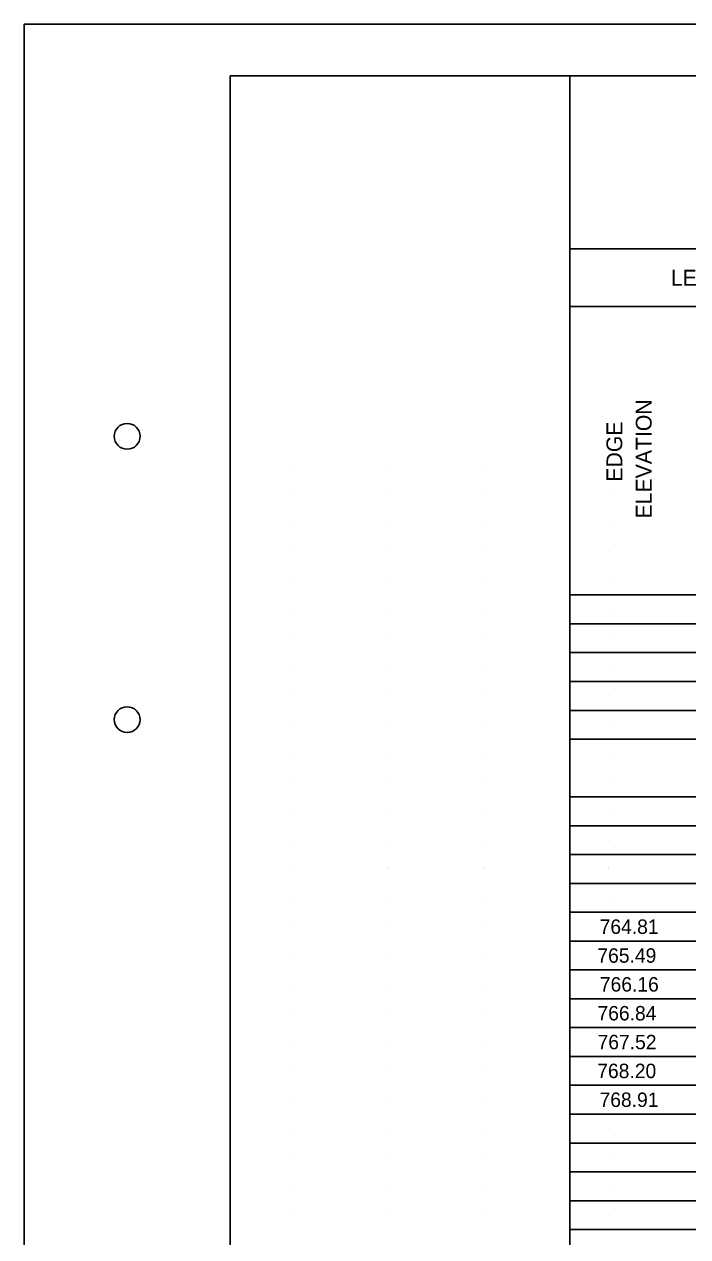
# Model space of a CAD drawing. Extents: x -15.4 to 18.6, y -12.6 to 9.4.
# Drawn here: x -15.36 to -8.91, y -2.38 to 9.39 of the extents above; entities that cross this region are included whole.
import ezdxf

# ---------------------------------------------------------------- set-up
doc = ezdxf.new("R2010")
doc.units = 0
for name, color, linetype in [('SH_Border', 7, 'Continuous'), ('SH_Cut_Line', 7, 'Continuous'), ('SH_Data', 7, 'Continuous'), ('SH_Text', 7, 'Continuous')]:
    doc.layers.add(name, color=color, linetype=linetype)

msp = doc.modelspace()

# ---------------------------------------------------------------- linework, layer by layer
at = {"layer": 'SH_Border'}
msp.add_lwpolyline([(-13.357, 8.888), (18.143, 8.888), (18.143, -12.112), (-13.357, -12.112)], close=True, dxfattribs=at)
for centre in [(-14.357, 5.388), (-14.357, 2.638)]:
    msp.add_circle(centre, 0.125, dxfattribs=at)
at = {"layer": 'SH_Cut_Line'}
msp.add_lwpolyline([(-15.357, -12.612), (18.643, -12.612), (18.643, 9.388), (-15.357, 9.388)], close=True, dxfattribs=at)
at = {"layer": 'SH_Data'}
for p, q in [((-10.059, 8.888), (13.939, 8.888)), ((-10.059, 8.888), (-10.059, -6.232)), ((-10.059, 7.208), (13.939, 7.208)), ((-10.059, 6.648), (12.637, 6.648)), ((-12.782, 5.108), (-12.782, 5.108)), ((-11.832, 5.108), (-11.832, 5.108)), ((-10.882, 5.108), (-10.882, 5.108)), ((-9.682, 5.108), (-9.682, 5.108)), ((-12.782, 4.828), (-12.782, 4.828)), ((-11.832, 4.828), (-11.832, 4.828)), ((-10.882, 4.828), (-10.882, 4.828)), ((-9.682, 4.828), (-9.682, 4.828)), ((-12.782, 4.548), (-12.782, 4.548)), ((-11.832, 4.548), (-11.832, 4.548)), ((-10.882, 4.548), (-10.882, 4.548)), ((-9.682, 4.548), (-9.682, 4.548)), ((-12.782, 4.268), (-12.782, 4.268)), ((-11.832, 4.268), (-11.832, 4.268)), ((-10.882, 4.268), (-10.882, 4.268)), ((-9.682, 4.268), (-9.682, 4.268)), ((-12.782, 3.988), (-12.782, 3.988)), ((-11.832, 3.988), (-11.832, 3.988)), ((-10.882, 3.988), (-10.882, 3.988)), ((-9.682, 3.988), (-9.682, 3.988)), ((-10.059, 3.848), (13.939, 3.848)), ((-12.782, 3.708), (-12.782, 3.708)), ((-11.832, 3.708), (-11.832, 3.708)), ((-10.882, 3.708), (-10.882, 3.708)), ((-9.682, 3.708), (-9.682, 3.708)), ((-10.059, 3.568), (13.939, 3.568)), ((-12.782, 3.428), (-12.782, 3.428)), ((-11.832, 3.428), (-11.832, 3.428)), ((-10.882, 3.428), (-10.882, 3.428)), ((-9.682, 3.428), (-9.682, 3.428)), ((-10.059, 3.288), (13.939, 3.288)), ((-12.782, 3.148), (-12.782, 3.148)), ((-11.832, 3.148), (-11.832, 3.148)), ((-10.882, 3.148), (-10.882, 3.148)), ((-9.682, 3.148), (-9.682, 3.148)), ((-10.059, 3.008), (13.939, 3.008)), ((-12.782, 2.868), (-12.782, 2.868)), ((-11.832, 2.868), (-11.832, 2.868)), ((-10.882, 2.868), (-10.882, 2.868)), ((-9.682, 2.868), (-9.682, 2.868)), ((-10.059, 2.728), (13.939, 2.728)), ((-12.782, 2.588), (-12.782, 2.588)), ((-11.832, 2.588), (-11.832, 2.588)), ((-10.882, 2.588), (-10.882, 2.588)), ((-9.682, 2.588), (-9.682, 2.588)), ((-10.059, 2.448), (13.939, 2.448)), ((-12.782, 2.308), (-12.782, 2.308)), ((-11.832, 2.308), (-11.832, 2.308)), ((-10.882, 2.308), (-10.882, 2.308)), ((-9.682, 2.308), (-9.682, 2.308)), ((-12.782, 2.028), (-12.782, 2.028)), ((-11.832, 2.028), (-11.832, 2.028)), ((-10.882, 2.028), (-10.882, 2.028)), ((-9.682, 2.028), (-9.682, 2.028)), ((-10.059, 1.888), (13.939, 1.888)), ((-12.782, 1.748), (-12.782, 1.748)), ((-12.782, 1.748), (-12.782, 1.748)), ((-11.832, 1.748), (-11.832, 1.748)), ((-11.832, 1.748), (-11.832, 1.748)), ((-10.882, 1.748), (-10.882, 1.748)), ((-10.882, 1.748), (-10.882, 1.748)), ((-9.682, 1.748), (-9.682, 1.748)), ((-9.682, 1.748), (-9.682, 1.748)), ((-10.059, 1.608), (13.939, 1.608)), ((-12.782, 1.468), (-12.782, 1.468)), ((-12.782, 1.468), (-12.782, 1.468)), ((-11.832, 1.468), (-11.832, 1.468)), ((-11.832, 1.468), (-11.832, 1.468)), ((-10.882, 1.468), (-10.882, 1.468)), ((-10.882, 1.468), (-10.882, 1.468)), ((-9.682, 1.468), (-9.682, 1.468)), ((-9.682, 1.468), (-9.682, 1.468)), ((-10.059, 1.328), (13.939, 1.328)), ((-12.785, 1.188), (-12.785, 1.188)), ((-12.785, 1.188), (-12.785, 1.188)), ((-12.782, 1.188), (-12.782, 1.188)), ((-11.835, 1.188), (-11.835, 1.188)), ((-11.835, 1.188), (-11.835, 1.188)), ((-11.832, 1.188), (-11.832, 1.188)), ((-10.885, 1.188), (-10.885, 1.188)), ((-10.885, 1.188), (-10.885, 1.188)), ((-10.882, 1.188), (-10.882, 1.188)), ((-9.685, 1.188), (-9.685, 1.188)), ((-9.685, 1.188), (-9.685, 1.188)), ((-9.682, 1.188), (-9.682, 1.188)), ((-10.059, 1.048), (13.939, 1.048)), ((-12.782, 0.908), (-12.782, 0.908)), ((-11.832, 0.908), (-11.832, 0.908)), ((-10.882, 0.908), (-10.882, 0.908)), ((-9.682, 0.908), (-9.682, 0.908)), ((-10.059, 0.768), (13.939, 0.768)), ((-12.782, 0.628), (-12.782, 0.628)), ((-11.832, 0.628), (-11.832, 0.628)), ((-10.882, 0.628), (-10.882, 0.628)), ((-9.682, 0.628), (-9.682, 0.628)), ((-10.059, 0.488), (13.939, 0.488)), ((-12.782, 0.348), (-12.782, 0.348)), ((-11.832, 0.348), (-11.832, 0.348)), ((-10.882, 0.348), (-10.882, 0.348)), ((-9.682, 0.348), (-9.682, 0.348)), ((-10.059, 0.208), (13.939, 0.208)), ((-12.782, 0.068), (-12.782, 0.068)), ((-11.832, 0.068), (-11.832, 0.068)), ((-10.882, 0.068), (-10.882, 0.068)), ((-9.682, 0.068), (-9.682, 0.068)), ((-10.059, -0.072), (13.939, -0.072)), ((-12.782, -0.212), (-12.782, -0.212)), ((-11.832, -0.212), (-11.832, -0.212)), ((-10.882, -0.212), (-10.882, -0.212)), ((-9.682, -0.212), (-9.682, -0.212)), ((-10.059, -0.352), (13.939, -0.352)), ((-12.782, -0.492), (-12.782, -0.492)), ((-11.832, -0.492), (-11.832, -0.492)), ((-10.882, -0.492), (-10.882, -0.492)), ((-9.682, -0.492), (-9.682, -0.492)), ((-10.059, -0.632), (13.939, -0.632)), ((-12.782, -0.772), (-12.782, -0.772)), ((-11.832, -0.772), (-11.832, -0.772)), ((-10.882, -0.772), (-10.882, -0.772)), ((-9.682, -0.772), (-9.682, -0.772)), ((-10.059, -0.912), (13.939, -0.912)), ((-12.782, -1.052), (-12.782, -1.052)), ((-11.832, -1.052), (-11.832, -1.052)), ((-10.882, -1.052), (-10.882, -1.052)), ((-9.682, -1.052), (-9.682, -1.052)), ((-10.059, -1.192), (13.939, -1.192)), ((-12.782, -1.332), (-12.782, -1.332)), ((-11.832, -1.332), (-11.832, -1.332)), ((-10.882, -1.332), (-10.882, -1.332)), ((-9.682, -1.332), (-9.682, -1.332)), ((-10.059, -1.472), (13.939, -1.472)), ((-12.782, -1.612), (-12.782, -1.612)), ((-11.832, -1.612), (-11.832, -1.612)), ((-10.882, -1.612), (-10.882, -1.612)), ((-9.682, -1.612), (-9.682, -1.612)), ((-10.059, -1.752), (13.939, -1.752)), ((-12.782, -1.892), (-12.782, -1.892)), ((-11.832, -1.892), (-11.832, -1.892)), ((-10.882, -1.892), (-10.882, -1.892)), ((-9.682, -1.892), (-9.682, -1.892)), ((-10.059, -2.032), (13.939, -2.032)), ((-12.782, -2.172), (-12.782, -2.172)), ((-11.832, -2.172), (-11.832, -2.172)), ((-10.882, -2.172), (-10.882, -2.172)), ((-9.682, -2.172), (-9.682, -2.172)), ((-10.059, -2.312), (13.939, -2.312))]:
    msp.add_line(p, q, dxfattribs=at)

# ---------------------------------------------------------------- texts
at = {"layer": 'SH_Text'}
for s, height, p in [('LEFT PARKING LANE', 0.154, (-9.076, 6.851)), ('764.81', 0.14, (-9.768, 0.558)), ('765.49', 0.14, (-9.79, 0.278)), ('766.16', 0.14, (-9.766, -0.002)), ('766.84', 0.14, (-9.789, -0.282)), ('767.52', 0.14, (-9.788, -0.562)), ('768.20', 0.14, (-9.791, -0.842)), ('768.91', 0.14, (-9.769, -1.122))]:
    msp.add_text(s, height=height, dxfattribs=at).set_placement(p)
for s, p in [('ELEVATION', (-9.263, 4.591)), ('EDGE', (-9.548, 4.948))]:
    msp.add_text(s, height=0.154, rotation=90, dxfattribs=at).set_placement(p)

doc.saveas('drawing.dxf')
